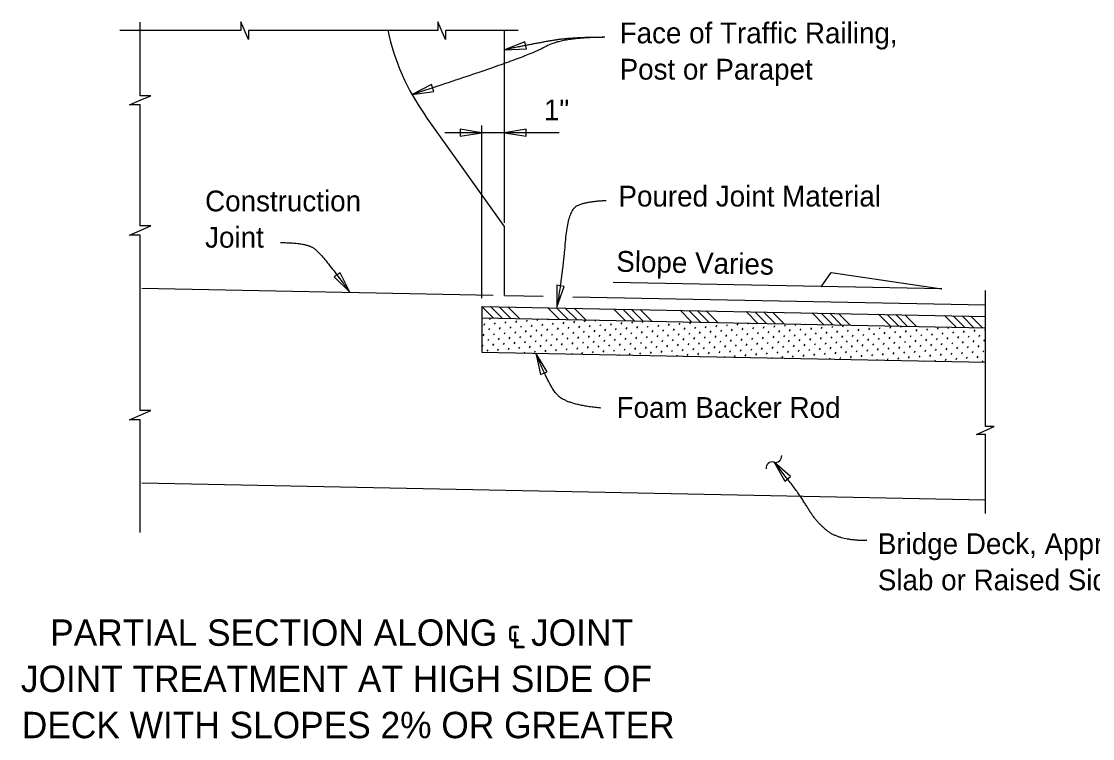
# Model space of a CAD drawing. Extents: x -7.9 to 27, y -3.1 to 14.6.
# Drawn here: x 5.908 to 9.806, y 11.645 to 14.253 of the extents above; entities that cross this region are included whole.
import ezdxf

# ---------------------------------------------------------------- set-up
doc = ezdxf.new("R2010")
doc.units = 0
for name, color, linetype in [('Border', 7, 'Continuous'), ('Patterning', 7, 'Continuous'), ('PlotBorder_dp', 7, 'Continuous'), ('SupstrConc_h', 7, 'Continuous'), ('TextMisc', 7, 'Continuous')]:
    doc.layers.add(name, color=color, linetype=linetype)

msp = doc.modelspace()

# ---------------------------------------------------------------- linework, layer by layer
at = {"layer": 'Patterning'}
for p, q in [((7.6665, 13.5205), (7.6665, 14.2208)), ((7.6665, 13.5068), (7.3782, 13.9104)), ((7.6664, 13.2569), (7.6664, 13.5069)), ((7.6665, 13.257), (7.8072, 13.2541)), ((7.9152, 13.252), (9.4165, 13.2219)), ((6.346, 12.575), (9.4165, 12.5136))]:
    msp.add_line(p, q, dxfattribs=at)
msp.add_arc((8.0563, 14.3948), 0.8333, 192.0469, 215.5377, dxfattribs=at)
at = {"layer": 'PlotBorder_dp'}
for p, q in [((7.8648, 13.8485), (7.4488, 13.8485)), ((7.5831, 13.2464), (7.5831, 13.8743))]:
    msp.add_line(p, q, dxfattribs=at)
for points in [[(6.9272, 14.2208), (6.7346, 14.2208), (6.7346, 14.1878), (6.7062, 14.2518), (6.7062, 14.2208), (6.2668, 14.2208)], [(6.3402, 13.5399), (6.3402, 13.9494), (6.3014, 13.9494), (6.3402, 13.9663), (6.3789, 13.9831), (6.3402, 13.9831), (6.3402, 14.2505)], [(7.7162, 14.2208), (7.4518, 14.2208), (7.4518, 14.1878), (7.4235, 14.2518), (7.4235, 14.2208), (6.9272, 14.2208)], [(6.3402, 13.1987), (6.3402, 13.4756), (6.3014, 13.4756), (6.3402, 13.4925), (6.3789, 13.5094), (6.3402, 13.5094), (6.3402, 13.819)], [(8.818, 13.2877), (8.8545, 13.3401), (9.258, 13.2802), (8.0614, 13.3041)], [(9.4165, 12.4631), (9.4165, 12.7513), (9.3834, 12.7513), (9.4474, 12.7796), (9.4165, 12.7796), (9.4165, 13.2747)], [(6.3402, 12.3944), (6.3402, 12.804), (6.3014, 12.804), (6.3402, 12.8209), (6.3789, 12.8377), (6.3402, 12.8377), (6.3402, 13.1987)]]:
    msp.add_lwpolyline(points, dxfattribs=at)
for points in [[(7.6663, 14.15), (7.7455, 14.1531), (7.7401, 14.179)], [(7.3302, 13.9875), (7.4086, 13.9989), (7.4005, 14.0241)], [(7.583, 13.8486), (7.5049, 13.8618), (7.5049, 13.8354)], [(7.6664, 13.8486), (7.7445, 13.8354), (7.7445, 13.8618)], [(7.1031, 13.2682), (7.0682, 13.3393), (7.0467, 13.3238)], [(7.8567, 13.2144), (7.8826, 13.2892), (7.8565, 13.2936)], [(7.7806, 13.0462), (7.7971, 12.9687), (7.8217, 12.9785)], [(8.6467, 12.6502), (8.6865, 12.5817), (8.7069, 12.5987)]]:
    msp.add_lwpolyline(points, close=True, dxfattribs=at)
for centre, start, end in [((8.6524, 12.6716), 254.5069, 6.2341), ((8.6405, 12.6285), 74.5069, 186.2341)]:
    msp.add_arc(centre, 0.0224, start, end, dxfattribs=at)
for points in [[(8.0309, 14.1954), (7.8722, 14.1954), (7.7513, 14.1236), (7.3302, 13.9875)], [(8.0309, 14.1954), (7.9138, 14.1954), (7.7835, 14.1746), (7.6664, 14.15)], [(8.0364, 13.601), (7.9651, 13.5985), (7.8961, 13.5665), (7.8789, 13.3474), (7.8568, 13.2144)], [(6.8508, 13.4489), (6.9403, 13.4489), (7.0011, 13.4096), (7.1031, 13.2681)], [(8.017, 12.8468), (7.8914, 12.8591), (7.8274, 12.928), (7.7807, 13.0462)], [(8.9848, 12.3649), (8.8885, 12.3649), (8.7997, 12.431), (8.7317, 12.5482), (8.6467, 12.6502)]]:
    msp.add_open_spline(points, degree=2, dxfattribs=at)
at = {"layer": 'SupstrConc_h'}
msp.add_line((6.3462, 13.2833), (7.6248, 13.2577), dxfattribs=at)
at = {"layer": 'TextMisc'}
for p, q in [((7.5831, 13.2169), (7.5831, 13.0502)), ((7.5831, 13.2169), (9.4165, 13.1802)), ((7.5831, 13.2169), (7.6257, 13.1744)), ((7.6149, 13.2163), (7.6575, 13.1737)), ((7.6468, 13.2156), (7.6893, 13.1731)), ((7.6786, 13.215), (7.7212, 13.1724)), ((7.5831, 13.1752), (9.4165, 13.1385)), ((7.6125, 13.1696), (7.6154, 13.1746)), ((7.8237, 13.2121), (7.8662, 13.1695)), ((7.8555, 13.2115), (7.8981, 13.1689)), ((7.8874, 13.2108), (7.9299, 13.1683)), ((7.9192, 13.2102), (7.9618, 13.1676)), ((8.0643, 13.2073), (8.1068, 13.1647)), ((8.0961, 13.2067), (8.1387, 13.1641)), ((8.1279, 13.206), (8.1705, 13.1635)), ((8.1598, 13.2054), (8.2023, 13.1628)), ((8.3049, 13.2025), (8.3474, 13.1599)), ((8.3367, 13.2018), (8.3793, 13.1593)), ((8.3685, 13.2012), (8.4111, 13.1586)), ((8.4004, 13.2006), (8.4429, 13.158)), ((8.5455, 13.1977), (8.588, 13.1551)), ((8.5773, 13.197), (8.6199, 13.1545)), ((8.6091, 13.1964), (8.6517, 13.1538)), ((8.641, 13.1957), (8.6835, 13.1532)), ((8.786, 13.1928), (8.8286, 13.1503)), ((8.8179, 13.1922), (8.8604, 13.1496)), ((8.8497, 13.1916), (8.8923, 13.149)), ((8.8816, 13.1909), (8.9241, 13.1484)), ((9.0266, 13.188), (9.0692, 13.1455)), ((9.0585, 13.1874), (9.101, 13.1448)), ((9.0903, 13.1868), (9.1329, 13.1442)), ((9.1222, 13.1861), (9.1647, 13.1436)), ((9.2672, 13.1832), (9.3098, 13.1407)), ((9.2991, 13.1826), (9.3416, 13.14)), ((9.3309, 13.1819), (9.3735, 13.1394)), ((9.3627, 13.1813), (9.4053, 13.1387)), ((7.5916, 13.1487), (7.5948, 13.1543)), ((7.6093, 13.131), (7.6125, 13.1366)), ((7.6302, 13.1519), (7.6335, 13.1575)), ((7.648, 13.1342), (7.6512, 13.1398)), ((7.6512, 13.1729), (7.6518, 13.1738)), ((7.6689, 13.1552), (7.6722, 13.1608)), ((7.6866, 13.1374), (7.6899, 13.143)), ((7.7076, 13.1584), (7.7108, 13.164)), ((7.7253, 13.1407), (7.7285, 13.1463)), ((7.7463, 13.1616), (7.7495, 13.1672)), ((7.764, 13.1439), (7.7672, 13.1495)), ((7.7849, 13.1649), (7.7882, 13.1705)), ((7.8026, 13.1472), (7.8059, 13.1528)), ((7.8236, 13.1681), (7.8249, 13.1704)), ((7.8413, 13.1504), (7.8446, 13.156)), ((7.859, 13.1327), (7.8623, 13.1383)), ((7.88, 13.1536), (7.8832, 13.1592)), ((7.8977, 13.1359), (7.9009, 13.1415)), ((7.9187, 13.1569), (7.9219, 13.1625)), ((7.9364, 13.1392), (7.9396, 13.1448)), ((7.9573, 13.1601), (7.9606, 13.1657)), ((7.975, 13.1424), (7.9783, 13.148)), ((7.996, 13.1634), (7.998, 13.1669)), ((8.0137, 13.1457), (8.0169, 13.1513)), ((8.0524, 13.1489), (8.0556, 13.1545)), ((8.0701, 13.1312), (8.0733, 13.1368)), ((8.091, 13.1521), (8.0943, 13.1577)), ((8.1088, 13.1344), (8.112, 13.14)), ((8.1297, 13.1554), (8.133, 13.161)), ((8.1474, 13.1377), (8.1507, 13.1433)), ((8.1684, 13.1586), (8.1712, 13.1634)), ((8.1861, 13.1409), (8.1893, 13.1465)), ((8.2071, 13.1619), (8.2076, 13.1627)), ((8.2248, 13.1441), (8.228, 13.1497)), ((8.2634, 13.1474), (8.2667, 13.153)), ((8.2812, 13.1297), (8.2844, 13.1353)), ((8.3021, 13.1506), (8.3054, 13.1562)), ((8.3198, 13.1329), (8.3231, 13.1385)), ((8.3408, 13.1539), (8.344, 13.1595)), ((8.3585, 13.1362), (8.3617, 13.1418)), ((8.3795, 13.1571), (8.3807, 13.1592)), ((8.3972, 13.1394), (8.4004, 13.145)), ((8.4358, 13.1426), (8.4391, 13.1482)), ((8.4745, 13.1459), (8.4777, 13.1515)), ((8.5132, 13.1491), (8.5164, 13.1547)), ((8.5309, 13.1314), (8.5341, 13.137)), ((8.5518, 13.1524), (8.5538, 13.1558)), ((8.5696, 13.1346), (8.5728, 13.1402)), ((8.6082, 13.1379), (8.6115, 13.1435)), ((8.6469, 13.1411), (8.6501, 13.1467)), ((8.6856, 13.1444), (8.6888, 13.15)), ((8.7242, 13.1476), (8.727, 13.1523)), ((8.742, 13.1299), (8.7452, 13.1355)), ((8.7629, 13.1508), (8.7633, 13.1516)), ((8.7806, 13.1331), (8.7839, 13.1387)), ((8.8193, 13.1364), (8.8225, 13.142)), ((8.858, 13.1396), (8.8612, 13.1452)), ((8.8966, 13.1429), (8.8999, 13.1485)), ((8.9353, 13.1461), (8.9365, 13.1481)), ((8.9917, 13.1316), (8.9949, 13.1372)), ((9.0304, 13.1349), (9.0336, 13.1405)), ((9.069, 13.1381), (9.0723, 13.1437)), ((9.1077, 13.1413), (9.1096, 13.1447)), ((9.2028, 13.1301), (9.206, 13.1357)), ((9.2414, 13.1334), (9.2447, 13.139)), ((9.2801, 13.1366), (9.2828, 13.1412)), ((9.3188, 13.1398), (9.3191, 13.1405)), ((7.5883, 13.11), (7.5916, 13.1156)), ((7.6061, 13.0923), (7.6093, 13.0979)), ((7.627, 13.1132), (7.6302, 13.1188)), ((7.6447, 13.0955), (7.648, 13.1011)), ((7.6657, 13.1165), (7.6689, 13.1221)), ((7.6834, 13.0988), (7.6866, 13.1044)), ((7.7043, 13.1197), (7.7076, 13.1253)), ((7.7221, 13.102), (7.7253, 13.1076)), ((7.743, 13.123), (7.7463, 13.1286)), ((7.7607, 13.1053), (7.764, 13.1109)), ((7.7817, 13.1262), (7.7849, 13.1318)), ((7.7994, 13.1085), (7.8026, 13.1141)), ((7.8171, 13.0908), (7.8204, 13.0964)), ((7.8204, 13.1295), (7.8236, 13.135)), ((7.8381, 13.1117), (7.8413, 13.1173)), ((7.8558, 13.094), (7.859, 13.0996)), ((7.8767, 13.115), (7.88, 13.1206)), ((7.8945, 13.0973), (7.8977, 13.1029)), ((7.9154, 13.1182), (7.9187, 13.1238)), ((7.9331, 13.1005), (7.9364, 13.1061)), ((7.9541, 13.1215), (7.9573, 13.1271)), ((7.9718, 13.1037), (7.975, 13.1093)), ((7.9928, 13.1247), (7.996, 13.1303)), ((8.0105, 13.107), (8.0137, 13.1126)), ((8.0314, 13.1279), (8.0347, 13.1335)), ((8.0491, 13.1102), (8.0524, 13.1158)), ((8.0669, 13.0925), (8.0701, 13.0981)), ((8.0878, 13.1135), (8.091, 13.1191)), ((8.1055, 13.0958), (8.1088, 13.1014)), ((8.1265, 13.1167), (8.1297, 13.1223)), ((8.1442, 13.099), (8.1474, 13.1046)), ((8.1651, 13.1199), (8.1684, 13.1255)), ((8.1829, 13.1022), (8.1861, 13.1078)), ((8.2038, 13.1232), (8.2071, 13.1288)), ((8.2215, 13.1055), (8.2248, 13.1111)), ((8.2425, 13.1264), (8.2457, 13.132)), ((8.2602, 13.1087), (8.2634, 13.1143)), ((8.2779, 13.091), (8.2812, 13.0966)), ((8.2989, 13.112), (8.3021, 13.1176)), ((8.3166, 13.0942), (8.3198, 13.0998)), ((8.3375, 13.1152), (8.3408, 13.1208)), ((8.3553, 13.0975), (8.3585, 13.1031)), ((8.3762, 13.1184), (8.3795, 13.124)), ((8.3939, 13.1007), (8.3972, 13.1063)), ((8.4149, 13.1217), (8.4181, 13.1273)), ((8.4326, 13.104), (8.4358, 13.1096)), ((8.4535, 13.1249), (8.4568, 13.1305)), ((8.4713, 13.1072), (8.4745, 13.1128)), ((8.4922, 13.1282), (8.4955, 13.1338)), ((8.5099, 13.1104), (8.5132, 13.116)), ((8.5276, 13.0927), (8.5309, 13.0983)), ((8.5486, 13.1137), (8.5518, 13.1193)), ((8.5663, 13.096), (8.5696, 13.1016)), ((8.5873, 13.1169), (8.5905, 13.1225)), ((8.605, 13.0992), (8.6082, 13.1048)), ((8.6259, 13.1202), (8.6292, 13.1258)), ((8.6437, 13.1025), (8.6469, 13.1081)), ((8.6646, 13.1234), (8.6679, 13.129)), ((8.6823, 13.1057), (8.6856, 13.1113)), ((8.7033, 13.1267), (8.7065, 13.1322)), ((8.721, 13.1089), (8.7242, 13.1145)), ((8.7387, 13.0912), (8.742, 13.0968)), ((8.7597, 13.1122), (8.7629, 13.1178)), ((8.7774, 13.0945), (8.7806, 13.1001)), ((8.7983, 13.1154), (8.8016, 13.121)), ((8.8161, 13.0977), (8.8193, 13.1033)), ((8.837, 13.1187), (8.8402, 13.1243)), ((8.8547, 13.1009), (8.858, 13.1065)), ((8.8757, 13.1219), (8.8789, 13.1275)), ((8.8934, 13.1042), (8.8966, 13.1098)), ((8.9143, 13.1251), (8.9176, 13.1307)), ((8.9321, 13.1074), (8.9353, 13.113)), ((8.953, 13.1284), (8.9563, 13.134)), ((8.9707, 13.1107), (8.974, 13.1163)), ((8.9884, 13.093), (8.9917, 13.0986)), ((9.0094, 13.1139), (9.0126, 13.1195)), ((9.0271, 13.0962), (9.0304, 13.1018)), ((9.0481, 13.1171), (9.0513, 13.1227)), ((9.0658, 13.0994), (9.069, 13.105)), ((9.0867, 13.1204), (9.09, 13.126)), ((9.1045, 13.1027), (9.1077, 13.1083)), ((9.1254, 13.1236), (9.1287, 13.1292)), ((9.1431, 13.1059), (9.1464, 13.1115)), ((9.1641, 13.1269), (9.1673, 13.1325)), ((9.1818, 13.1092), (9.185, 13.1148)), ((9.1995, 13.0914), (9.2028, 13.097)), ((9.2205, 13.1124), (9.2237, 13.118)), ((9.2382, 13.0947), (9.2414, 13.1003)), ((9.2591, 13.1156), (9.2624, 13.1212)), ((9.2769, 13.0979), (9.2801, 13.1035)), ((9.2978, 13.1189), (9.301, 13.1245)), ((9.3155, 13.1012), (9.3188, 13.1068)), ((9.3365, 13.1221), (9.3397, 13.1277)), ((9.3542, 13.1044), (9.3574, 13.11)), ((9.3751, 13.1254), (9.3784, 13.131)), ((9.3929, 13.1076), (9.3961, 13.1132)), ((9.4138, 13.1286), (9.4165, 13.1333)), ((7.5851, 13.0713), (7.5883, 13.0769)), ((7.6028, 13.0536), (7.6061, 13.0592)), ((7.6238, 13.0746), (7.627, 13.0802)), ((7.6415, 13.0569), (7.6447, 13.0625)), ((7.6624, 13.0778), (7.6657, 13.0834)), ((7.6802, 13.0601), (7.6834, 13.0657)), ((7.7011, 13.0811), (7.7043, 13.0867)), ((7.7188, 13.0633), (7.7221, 13.0689)), ((7.7398, 13.0843), (7.743, 13.0899)), ((7.7575, 13.0666), (7.7607, 13.0722)), ((7.7784, 13.0875), (7.7817, 13.0931)), ((7.7962, 13.0698), (7.7994, 13.0754)), ((7.8139, 13.0521), (7.8171, 13.0577)), ((7.8348, 13.0731), (7.8381, 13.0787)), ((7.8525, 13.0554), (7.8558, 13.0609)), ((7.8735, 13.0763), (7.8767, 13.0819)), ((7.8912, 13.0586), (7.8945, 13.0642)), ((7.9122, 13.0795), (7.9154, 13.0851)), ((7.9299, 13.0618), (7.9331, 13.0674)), ((7.9508, 13.0828), (7.9541, 13.0884)), ((7.9686, 13.0651), (7.9718, 13.0707)), ((7.9895, 13.086), (7.9928, 13.0916)), ((8.0072, 13.0683), (8.0105, 13.0739)), ((8.0282, 13.0893), (8.0314, 13.0949)), ((8.0459, 13.0716), (8.0491, 13.0772)), ((8.0636, 13.0538), (8.0669, 13.0594)), ((8.0846, 13.0748), (8.0878, 13.0804)), ((8.1023, 13.0571), (8.1055, 13.0627)), ((8.1232, 13.078), (8.1265, 13.0836)), ((8.1409, 13.0603), (8.1442, 13.0659)), ((8.1619, 13.0813), (8.1651, 13.0869)), ((8.1796, 13.0636), (8.1829, 13.0692)), ((8.2006, 13.0845), (8.2038, 13.0901)), ((8.2183, 13.0668), (8.2215, 13.0724)), ((8.2392, 13.0878), (8.2425, 13.0934)), ((8.257, 13.07), (8.2602, 13.0756)), ((8.2747, 13.0523), (8.2779, 13.0579)), ((8.2956, 13.0733), (8.2989, 13.0789)), ((8.3133, 13.0556), (8.3166, 13.0612)), ((8.3343, 13.0765), (8.3375, 13.0821)), ((8.352, 13.0588), (8.3553, 13.0644)), ((8.373, 13.0798), (8.3762, 13.0854)), ((8.3907, 13.0621), (8.3939, 13.0677)), ((8.4116, 13.083), (8.4149, 13.0886)), ((8.4294, 13.0653), (8.4326, 13.0709)), ((8.4503, 13.0863), (8.4535, 13.0918)), ((8.468, 13.0685), (8.4713, 13.0741)), ((8.489, 13.0895), (8.4922, 13.0951)), ((8.5067, 13.0718), (8.5099, 13.0774)), ((8.5244, 13.0541), (8.5276, 13.0597)), ((8.5454, 13.075), (8.5486, 13.0806)), ((8.5631, 13.0573), (8.5663, 13.0629)), ((8.584, 13.0783), (8.5873, 13.0839)), ((8.6017, 13.0605), (8.605, 13.0661)), ((8.6227, 13.0815), (8.6259, 13.0871)), ((8.6404, 13.0638), (8.6437, 13.0694)), ((8.6614, 13.0847), (8.6646, 13.0903)), ((8.6791, 13.067), (8.6823, 13.0726)), ((8.7, 13.088), (8.7033, 13.0936)), ((8.7178, 13.0703), (8.721, 13.0759)), ((8.7355, 13.0526), (8.7387, 13.0582)), ((8.7564, 13.0735), (8.7597, 13.0791)), ((8.7741, 13.0558), (8.7774, 13.0614)), ((8.7951, 13.0767), (8.7983, 13.0823)), ((8.8128, 13.059), (8.8161, 13.0646)), ((8.8338, 13.08), (8.837, 13.0856)), ((8.8515, 13.0623), (8.8547, 13.0679)), ((8.8724, 13.0832), (8.8757, 13.0888)), ((8.8902, 13.0655), (8.8934, 13.0711)), ((8.9111, 13.0865), (8.9143, 13.0921)), ((8.9288, 13.0688), (8.9321, 13.0744)), ((8.9498, 13.0897), (8.953, 13.0953)), ((8.9675, 13.072), (8.9707, 13.0776)), ((8.9852, 13.0543), (8.9884, 13.0599)), ((9.0062, 13.0752), (9.0094, 13.0808)), ((9.0239, 13.0575), (9.0271, 13.0631)), ((9.0448, 13.0785), (9.0481, 13.0841)), ((9.0625, 13.0608), (9.0658, 13.0664)), ((9.0835, 13.0817), (9.0867, 13.0873)), ((9.1012, 13.064), (9.1045, 13.0696)), ((9.1222, 13.085), (9.1254, 13.0906)), ((9.1399, 13.0672), (9.1431, 13.0728)), ((9.1608, 13.0882), (9.1641, 13.0938)), ((9.1786, 13.0705), (9.1818, 13.0761)), ((9.1963, 13.0528), (9.1995, 13.0584)), ((9.2172, 13.0737), (9.2205, 13.0793)), ((9.2349, 13.056), (9.2382, 13.0616)), ((9.2559, 13.077), (9.2591, 13.0826)), ((9.2736, 13.0593), (9.2769, 13.0649)), ((9.2946, 13.0802), (9.2978, 13.0858)), ((9.3123, 13.0625), (9.3155, 13.0681)), ((9.3332, 13.0835), (9.3365, 13.089)), ((9.3509, 13.0657), (9.3542, 13.0713)), ((9.3719, 13.0867), (9.3751, 13.0923)), ((9.3896, 13.069), (9.3929, 13.0746)), ((9.4106, 13.0899), (9.4138, 13.0955)), ((7.5831, 13.0502), (9.4165, 13.0135)), ((7.701, 13.0478), (7.7011, 13.048)), ((7.7374, 13.0471), (7.7398, 13.0512)), ((7.7752, 13.0489), (7.7784, 13.0545)), ((7.9105, 13.0436), (7.9122, 13.0465)), ((7.9476, 13.0441), (7.9508, 13.0497)), ((7.9863, 13.0474), (7.9895, 13.053)), ((8.0249, 13.0506), (8.0282, 13.0562)), ((8.0837, 13.0402), (8.0846, 13.0417)), ((8.12, 13.0394), (8.1232, 13.045)), ((8.1587, 13.0426), (8.1619, 13.0482)), ((8.1973, 13.0458), (8.2006, 13.0514)), ((8.236, 13.0491), (8.2392, 13.0547)), ((8.2568, 13.0367), (8.257, 13.037)), ((8.2932, 13.036), (8.2956, 13.0402)), ((8.3311, 13.0379), (8.3343, 13.0435)), ((8.3697, 13.0411), (8.373, 13.0467)), ((8.4084, 13.0443), (8.4116, 13.0499)), ((8.4471, 13.0476), (8.4503, 13.0532)), ((8.4663, 13.0325), (8.468, 13.0355)), ((8.4857, 13.0508), (8.489, 13.0564)), ((8.5035, 13.0331), (8.5067, 13.0387)), ((8.5421, 13.0363), (8.5454, 13.0419)), ((8.5808, 13.0396), (8.584, 13.0452)), ((8.6195, 13.0428), (8.6227, 13.0484)), ((8.6395, 13.029), (8.6404, 13.0307)), ((8.6581, 13.0461), (8.6614, 13.0517)), ((8.6758, 13.0284), (8.6791, 13.034)), ((8.6968, 13.0493), (8.7, 13.0549)), ((8.7145, 13.0316), (8.7178, 13.0372)), ((8.7532, 13.0348), (8.7564, 13.0404)), ((8.7919, 13.0381), (8.7951, 13.0437)), ((8.8126, 13.0256), (8.8128, 13.026)), ((8.8305, 13.0413), (8.8338, 13.0469)), ((8.849, 13.0249), (8.8515, 13.0292)), ((8.8692, 13.0446), (8.8724, 13.0502)), ((8.8869, 13.0268), (8.8902, 13.0324)), ((8.9079, 13.0478), (8.9111, 13.0534)), ((8.9256, 13.0301), (8.9288, 13.0357)), ((8.9465, 13.051), (8.9498, 13.0566)), ((8.9643, 13.0333), (8.9675, 13.0389)), ((9.0029, 13.0366), (9.0062, 13.0422)), ((9.0221, 13.0214), (9.0239, 13.0245)), ((9.0416, 13.0398), (9.0448, 13.0454)), ((9.0593, 13.0221), (9.0625, 13.0277)), ((9.0803, 13.0431), (9.0835, 13.0486)), ((9.098, 13.0253), (9.1012, 13.0309)), ((9.1189, 13.0463), (9.1222, 13.0519)), ((9.1366, 13.0286), (9.1399, 13.0342)), ((9.1576, 13.0495), (9.1608, 13.0551)), ((9.1753, 13.0318), (9.1786, 13.0374)), ((9.1952, 13.0179), (9.1963, 13.0197)), ((9.214, 13.0351), (9.2172, 13.0407)), ((9.2317, 13.0173), (9.2349, 13.0229)), ((9.2527, 13.0383), (9.2559, 13.0439)), ((9.2704, 13.0206), (9.2736, 13.0262)), ((9.2913, 13.0415), (9.2946, 13.0471)), ((9.309, 13.0238), (9.3123, 13.0294)), ((9.33, 13.0448), (9.3332, 13.0504)), ((9.3477, 13.0271), (9.3509, 13.0327)), ((9.3687, 13.048), (9.3719, 13.0536)), ((9.3864, 13.0303), (9.3896, 13.0359)), ((9.4073, 13.0513), (9.4106, 13.0569)), ((9.3684, 13.0145), (9.3687, 13.015)), ((9.4047, 13.0137), (9.4073, 13.0182))]:
    msp.add_line(p, q, dxfattribs=at)

# ---------------------------------------------------------------- texts
at = {"layer": 'Border'}
for s, p in [('1"', (7.8094, 13.8934)), ('Poured Joint Material', (8.0807, 13.58)), ('Foam Backer Rod', (8.074, 12.8114))]:
    msp.add_text(s, height=0.0756, dxfattribs=at).set_placement(p)
msp.add_text('Slope Varies', height=0.0756, rotation=358.8543, dxfattribs=at).set_placement((8.0722, 13.3432))
at = {"layer": 'PlotBorder_dp'}
for s, height, p in [('Face of Traffic Railing, ', 0.0756, (8.085, 14.1736)), ('Post or Parapet', 0.0756, (8.085, 14.0416)), ('Construction ', 0.0756, (6.5766, 13.5624)), ('Joint', 0.0756, (6.5766, 13.4304)), ('Bridge Deck, Approach ', 0.0756, (9.0245, 12.3161)), ('Slab or Raised Sidewalk', 0.0756, (9.0245, 12.1841)), ('PARTIAL SECTION ALONG ℄ JOINT', 0.096, (6.0129, 11.9823)), ('JOINT TREATMENT AT HIGH SIDE OF', 0.096, (5.9062, 11.8143)), ('DECK WITH SLOPES 2% OR GREATER', 0.096, (5.9097, 11.6463))]:
    msp.add_text(s, height=height, dxfattribs=at).set_placement(p)

doc.saveas('drawing.dxf')
